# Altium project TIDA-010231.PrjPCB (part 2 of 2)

## Sheet TIDA-010231_Interface.SchDoc: Interface
size 431 x 279 mm; Date: Not shown in title block; ApprovedBy: Not shown in title block; CheckedBy: Not shown in title block; Author: Not shown in title block; CompanyName: Not shown in title block; Engineer: Not shown in title block; Organization: Not shown in title block; Address1: Not shown in title block; Address2: Not shown in title block; Address3: Not shown in title block; Address4: Not shown in title block; DocumentNumber: 5; Revision: Use project parameter SCH_Rev; SheetNumber: 5; SheetTotal: 6; PageSetup: Record=PageOptions¦CenterHorizontal=True¦CenterVertical=True¦PrintScale=1.00¦XCorrection=1.00¦YCorrection=1.00¦PrintKind=0¦BorderSize=5000000¦LeftOffset=0¦BottomOffset=0¦Orientation=2¦PaperLength=1000¦PaperWidth=1000¦Scale=100¦PaperSource=15¦PrintQuality=600¦MediaType=1¦DitherType=10¦PaperKind=Letter¦PrintScaleMode=1
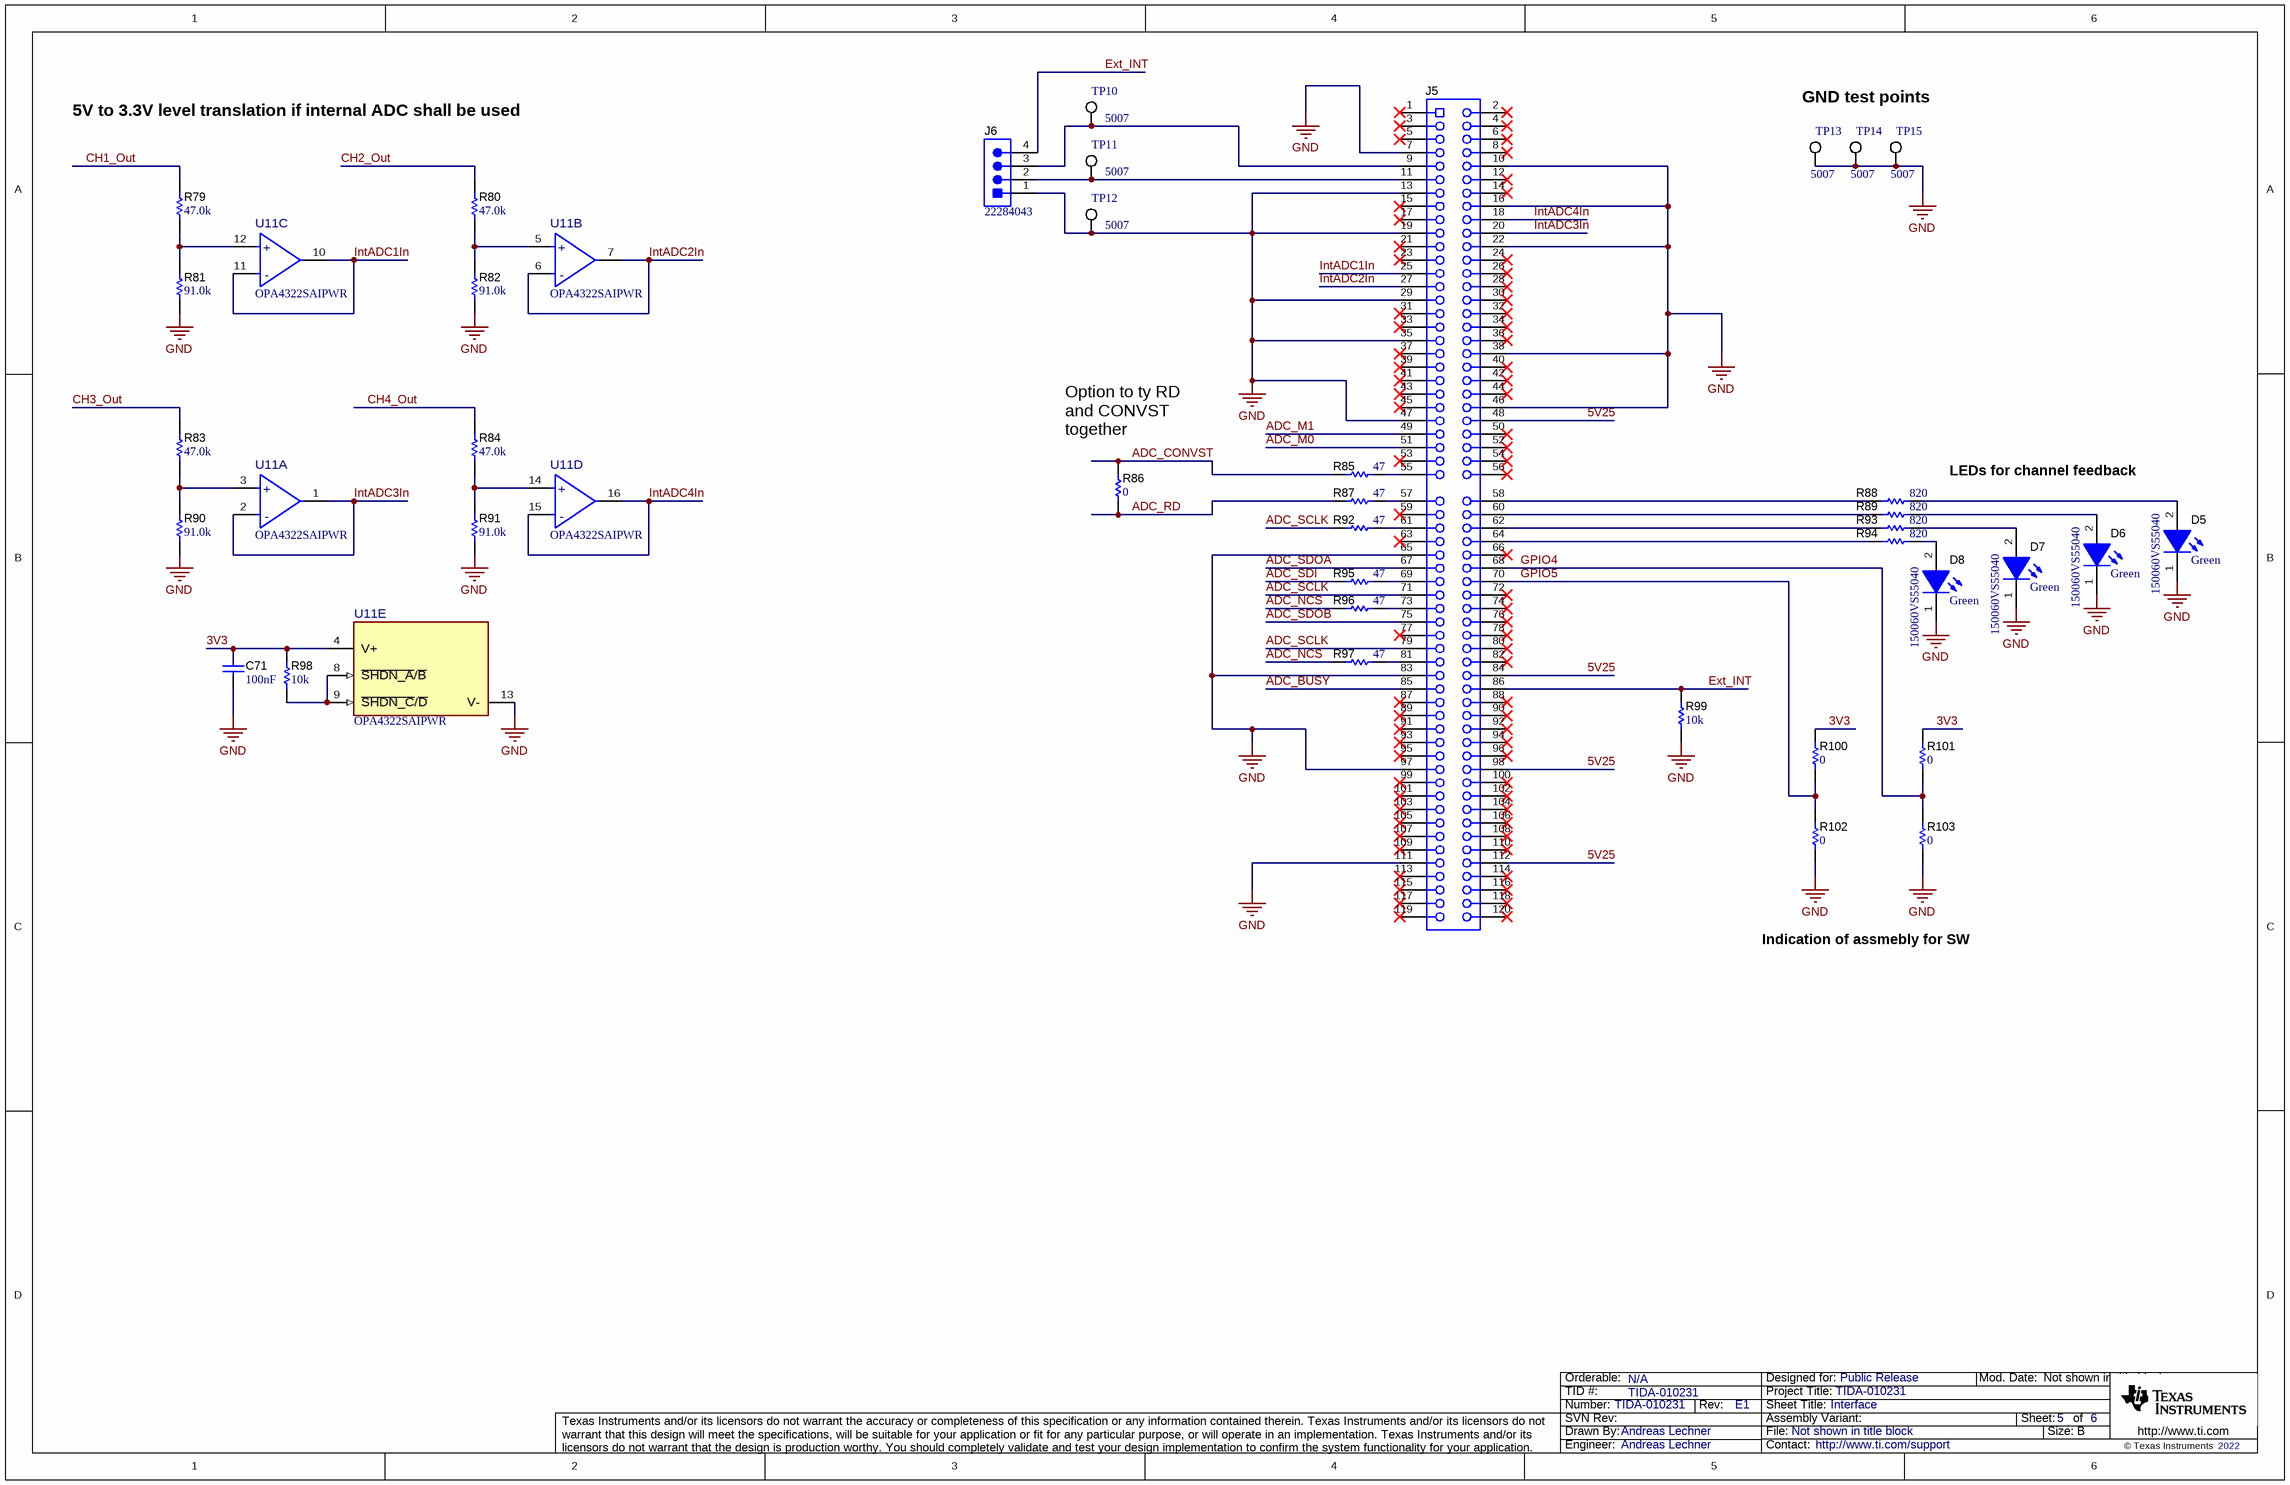
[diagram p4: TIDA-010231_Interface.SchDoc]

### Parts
C71  Cap_F: 100nF  [0603S]  (hidden comment: C0603C104K5RACAUTO)
D5  150060VS55040  value Green  [WL-SMCD-0603]
D6  150060VS55040  value Green  [WL-SMCD-0603]
D7  150060VS55040  value Green  [WL-SMCD-0603]
D8  150060VS55040  value Green  [WL-SMCD-0603]
J5  HSEC8-160-01-L-DV-A-BL  [controlCARD-120HSEC]  (value not drawn)
J6  22284043  [Molex_0022284043]
R79  ValueDisplayed: 47.0k  [0603S]  (hidden comment: CRCW060347K0FKEA)
R80  ValueDisplayed: 47.0k  [0603S]  (hidden comment: CRCW060347K0FKEA)
R81  ValueDisplayed: 91.0k  [0603S]  (hidden comment: RC0603FR-0791KL)
R82  ValueDisplayed: 91.0k  [0603S]  (hidden comment: RC0603FR-0791KL)
R83  ValueDisplayed: 47.0k  [0603S]  (hidden comment: CRCW060347K0FKEA)
R84  ValueDisplayed: 47.0k  [0603S]  (hidden comment: CRCW060347K0FKEA)
R85  ValueDisplayed: 47  [0402S]  (hidden comment: CRCW040247R0JNED)
R86  ValueDisplayed: 0  [0402S]  (hidden comment: CRCW04020000Z0ED)
R87  ValueDisplayed: 47  [0402S]  (hidden comment: CRCW040247R0JNED)
R88  ValueDisplayed: 820  [0603S]  (hidden comment: CRCW0603820RJNEA)
R89  ValueDisplayed: 820  [0603S]  (hidden comment: CRCW0603820RJNEA)
R90  ValueDisplayed: 91.0k  [0603S]  (hidden comment: RC0603FR-0791KL)
R91  ValueDisplayed: 91.0k  [0603S]  (hidden comment: RC0603FR-0791KL)
R92  ValueDisplayed: 47  [0402S]  (hidden comment: CRCW040247R0JNED)
R93  ValueDisplayed: 820  [0603S]  (hidden comment: CRCW0603820RJNEA)
R94  ValueDisplayed: 820  [0603S]  (hidden comment: CRCW0603820RJNEA)
R95  ValueDisplayed: 47  [0402S]  (hidden comment: CRCW040247R0JNED)
R96  ValueDisplayed: 47  [0402S]  (hidden comment: CRCW040247R0JNED)
R97  ValueDisplayed: 47  [0402S]  (hidden comment: CRCW040247R0JNED)
R98  ValueDisplayed: 10k  [0402S]  (hidden comment: CRCW040210K0JNED)
R99  ValueDisplayed: 10k  [0402S]  (hidden comment: CRCW040210K0JNED)
R100  ValueDisplayed: 0  [0603S]  (hidden comment: RMCF0603ZT0R00)
R101  ValueDisplayed: 0  [0603S]  (hidden comment: RMCF0603ZT0R00)
R102  ValueDisplayed: 0  [0603S]  (hidden comment: RMCF0603ZT0R00)
R103  ValueDisplayed: 0  [0603S]  (hidden comment: RMCF0603ZT0R00)
TP10  5007  [Keystone5007]
TP11  5007  [Keystone5007]
TP12  5007  [Keystone5007]
TP13  5007  [Keystone5007]
TP14  5007  [Keystone5007]
TP15  5007  [Keystone5007]
U11  OPA4322SAIPWR  [PW0016A-MFG]  (parts A,B,C,D,E of 5)

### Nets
GND: C71.2 D5.1(K) D6.1(K) D7.1(K) D8.1(K) J5.7 J5.10 J5.13 J5.16 J5.19 J5.22 J5.29 J5.35 J5.38 J5.46 J5.47 J5.65 J5.83 J5.97 J5.111 J6.1 R81.1 R82.1 R90.1 R91.1 R99.1 R102.1 R103.1 TP12.1 TP13.1 TP14.1 TP15.1 U11.13(V-)
3V3: C71.1 R98.2 R100.2 R101.1 U11.4(V+)
5V25: J5.48 J5.84 J5.98 J5.112
ADC_BUSY: J5.85
ADC_CONVST: R85.1 R86.2
ADC_M0: J5.51
ADC_M1: J5.49
ADC_NCS: R96.1 R97.1
ADC_RD: R86.1 R87.1
ADC_SCLK: J5.71 J5.79 R92.1
ADC_SDI: R95.1
ADC_SDOA: J5.67
ADC_SDOB: J5.75
CH1_Out: R79.2
CH2_Out: R80.2
CH3_Out: R83.2
CH4_Out: R84.2
Ext_INT: J5.86 J6.4 R99.2
GPIO4: J5.68 R101.2 R103.2
GPIO5: J5.70 R100.1 R102.2
IntADC1In: J5.25 U11.10(OUT_C) U11.11(-IN_C)
IntADC2In: J5.27 U11.6(-IN_B) U11.7(OUT_B)
IntADC3In: J5.20 U11.1(OUT_A) U11.2(-IN_A)
IntADC4In: J5.18 U11.15(-IN_D) U11.16(OUT_D)
NetD5_2: D5.2(A) R88.2
NetD6_2: D6.2(A) R89.2
NetD7_2: D7.2(A) R93.2
NetD8_2: D8.2(A) R94.2
NetJ5_9: J5.9 J6.3 TP10.1
NetJ5_11: J5.11 J6.2 TP11.1
NetJ5_55: J5.55 R85.2
NetJ5_57: J5.57 R87.2
NetJ5_58: J5.58 R88.1
NetJ5_60: J5.60 R89.1
NetJ5_61: J5.61 R92.2
NetJ5_62: J5.62 R93.1
NetJ5_64: J5.64 R94.1
NetJ5_69: J5.69 R95.2
NetJ5_73: J5.73 R96.2
NetJ5_81: J5.81 R97.2
NetR79_1: R79.1 R81.2 U11.12(+IN_C)
NetR80_1: R80.1 R82.2 U11.5(+IN_B)
NetR83_1: R83.1 R90.2 U11.3(+IN_A)
NetR84_1: R84.1 R91.2 U11.14(+IN_D)
NetR98_1: R98.1 U11.8(~{SHDN_A}/~{B}) U11.9(~{SHDN_C}/~{D})

Not connected (* = marked no-connect by the designer): J5 1* 2* 3* 4* 5* 6* 8* 12* 14* 15* 17* 21* 23* 24* 26* 28* 30* 31* 32* 33* 34* 36* 37* 39* 40* 41* 42* 43* 44* 45* 50* 52* 53* 54* 56* 59* 63* 66* 72* 74* 76* 77* 78* 80* 82* 87* 88* 89* 90* 91* 92* 93* 94* 95* 96* 99* 100* 101* 102* 103* 104* 105* 106* 107* 108* 109* 110* 113* 114* 115* 116* 117* 118* 119* 120*

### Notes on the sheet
- 5V to 3.3V level translation if internal ADC shall be used
- GND test points
- (near R86) Option to ty RD and CONVST together
- LEDs for channel feedback
- Indication of assmebly for SW

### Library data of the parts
C71 = CMP-0079602-1: CAP, CERM, 0.1 µF, 50 V,+/- 10%, X7R, AEC-Q200 Grade 1, 0603; Manufacturer: Kemet; TaMin_C: -55°C; Polarized: N; SizeAreaWB_mm2: 4.68; U/M: EA; Value: 0.1uF; TaMax_C: 125°C; SizeZ_mm: 1; SizeX_mm: 1.6; SizeY_mm: 0.8; Cap_Case: 0603; Value2: 50V; SizeArea_mm2: 1.28; AEC Qualified: Y; AEC Category: Q200; ValueDisplayed: 0.1µF
D5-D8 = CMP-0081648-2: LED, Green, SMD; Manufacturer: Wurth Elektronik; Type: AlInGaP; Vr_V: 5V; SizeZ_mm: 0.5; Tjmax_C: 115°C; Io_A: 20mA; Value1: 0.048W; Vf_V: 2V; SizeArea_mm2: 1.28; Angle: 140; SizeX_mm: 1.6; Ir_A: 10µA; Power_TotalModule: 48mW; SizeAreaWB_mm2: 4.68; SizeY_mm: 0.8
J5 = CMP-0003814-2: C2000 controlCARD-120HSEC connector, SMT; Manufacturer: Samtec; Note: The pin numbering does not match Samtec datasheet
J6 = CMP-0055331-1: Header, 2.54mm, 4x1, Tin, TH; Manufacturer: Molex; CNHeader: TRUE; Current_A: 4A; Shrouded: N; Gender: Male; Voltage_V: 250V; Row_Count: 1; Pitch_mm: 2.54; CT: FALSE; Cert_UL: Y
R79 R80 R83 R84 = CMP-0022438-4: RES, 47.0 k, 1%, 0.1 W, AEC-Q200 Grade 0, 0603; Manufacturer: Vishay-Dale; Power_W: 100mW; TempCo: 100 ppm/C; Value_Code: 47k0; Value: 47.0k; Res_ohm: 47k; SizeX_mm: 1.6; SizeY_mm: 0.8; SizeZ_mm: 1; Value2: 0.1W; SizeArea_mm2: 1.28; AEC Qualified: Y; AEC Grade: 0; AEC Category: Q200
R81 R82 R90 R91 = CMP-0023318-5: RES, 91.0 k, 1%, 0.1 W, 0603; Manufacturer: Yageo; Power_W: 100mW; TempCo: 100 ppm/C; Value_Code: 91k0; Value: 91.0k; Res_ohm: 91k; SizeX_mm: 1.6; SizeY_mm: 0.8; SizeZ_mm: 1; Value2: 0.1W; SizeArea_mm2: 1.28; AEC Qualified: N; AEC Category: Q200; SizeAreaWB_mm2: 4.68
R85 R87 R92 R95-R97 = CMP-0026936-3: RES, 47, 5%, 0.063 W, AEC-Q200 Grade 0, 0402; Manufacturer: Vishay-Dale; Power_W: 63mW; TempCo: 200 ppm/C; Value_Code: 47R0; Value: 47; EIA_Code: E24; SizeX_mm: 1; SizeY_mm: 0.5; SizeZ_mm: 0.6; Value2: 0.063W; AEC Qualified: Y; AEC Category: Q200; AEC Grade: 0
R86 = CMP-0026822-3: RES, 0, 5%, 0.063 W, AEC-Q200 Grade 0, 0402; Manufacturer: Vishay-Dale; Power_W: 63mW; TempCo: 200 ppm/C; Value_Code: 0000; Value: 0; EIA_Code: E24; SizeX_mm: 1; SizeY_mm: 0.5; SizeZ_mm: 0.6; Value2: 0.063W; AEC Qualified: Y; AEC Category: Q200
R88 R89 R93 R94 = CMP-0025859-4: RES, 820, 5%, 0.1 W, AEC-Q200 Grade 0, 0603; Manufacturer: Vishay-Dale; Power_W: 100mW; TempCo: 200 ppm/C; Value_Code: 820R; Value: 820; EIA_Code: E24; SizeX_mm: 1.6; SizeY_mm: 0.8; SizeZ_mm: 1; Value2: 0.1W; SizeArea_mm2: 1.28; AEC Qualified: Y; AEC Category: Q200; AEC Grade: 0
R98 R99 = CMP-0026825-5: RES, 10 k, 5%, 0.063 W, AEC-Q200 Grade 0, 0402; Manufacturer: Vishay-Dale; Power_W: 63mW; TempCo: 200 ppm/C; Value_Code: 10k0; Value: 10k; EIA_Code: E24; SizeX_mm: 1; SizeY_mm: 0.5; SizeZ_mm: 0.6; Value2: 0.063W; AEC Qualified: Y; AEC Category: Q200; AEC Grade: 0
R100-R103 = CMP-0023343-3: RES, 0, 1%, 0.1 W, AEC-Q200 Grade 0, 0603; Manufacturer: Stackpole Electronics Inc; Power_W: 100mW; TempCo: ppm/C; U/M: EA; Value: 0; SizeX_mm: 1.6; SizeY_mm: 0.8; SizeZ_mm: 1; Value2: 0.1W; SizeArea_mm2: 1.28; AEC Qualified: Y; AEC Category: Q200
TP10-TP15 = CMP-0055144-2: Test Point, Compact, White, TH; Manufacturer: Keystone Electronics; CNHeader: FALSE; Green_Lifecycle: Active; Green_REACh: Passed; ContactFinish: Silver; CT: TRUE
U11 = CMP-0093017-1: CMOS Amplifier 4 Circuit Rail-to-Rail 16-TSSOP; Manufacturer: Texas Instruments; TaMin_C: -40°C; Max Dual Supply Voltage: 2.75V; Voltage Gain: 130dB; Min Supply Voltage: 1.8V; TaMax_C: +125°C; Number Of Channels: 4; Input Bias Current: 0.0000002uA; AEC Qualified: No; TJmax_C: +150°C; Standoff Height: 0.05mm; Output Current Per Channel: 65mA; Response Time: 0.32us; Gain Bandwidth: 20MHz; Max Supply Voltage: 5.5V; Min Dual Supply Voltage: 900mV; Nominal Supply Current: 1.4mA; Ciiva Ids: 4369962; Import Ts: 1521861601; Input Offset Voltage: 0.5mV; SizeZ_mm: 1.2mm

## Sheet TIDA-010231_Hardware.SchDoc: Hardware
size 431 x 279 mm; Date: Not shown in title block; ApprovedBy: Not shown in title block; CheckedBy: Not shown in title block; Author: Not shown in title block; CompanyName: Not shown in title block; Engineer: Not shown in title block; Organization: Not shown in title block; Address1: Not shown in title block; Address2: Not shown in title block; Address3: Not shown in title block; Address4: Not shown in title block; DocumentNumber: 6; Revision: Use project parameter SCH_Rev; SheetNumber: 6; SheetTotal: 6; PageSetup: Record=PageOptions¦CenterHorizontal=True¦CenterVertical=True¦PrintScale=1.00¦XCorrection=1.00¦YCorrection=1.00¦PrintKind=0¦BorderSize=5000000¦LeftOffset=0¦BottomOffset=0¦Orientation=2¦PaperLength=1000¦PaperWidth=1000¦Scale=100¦PaperSource=15¦PrintQuality=600¦MediaType=1¦DitherType=10¦PaperKind=Letter¦PrintScaleMode=1
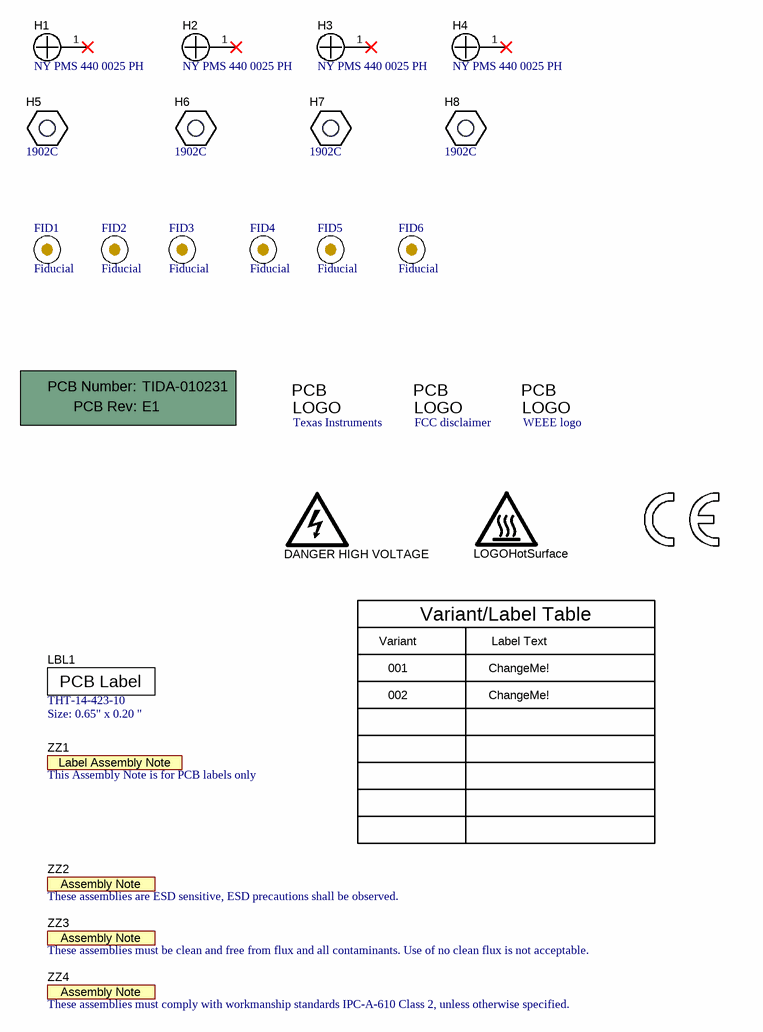
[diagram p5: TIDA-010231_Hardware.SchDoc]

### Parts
!PCB1  Printed Circuit Board  (value not drawn)  (mechanical)
FID1  Fiducial  [Fiducial10-30]
FID2  Fiducial  [Fiducial10-30]
FID3  Fiducial  [Fiducial10-30]
FID4  Fiducial  [Fiducial10-30]
FID5  Fiducial  [Fiducial10-30]
FID6  Fiducial  [Fiducial10-30]
H1  NY PMS 440 0025 PH  [NY PMS 440 0025 PH]
H2  NY PMS 440 0025 PH  [NY PMS 440 0025 PH]
H3  NY PMS 440 0025 PH  [NY PMS 440 0025 PH]
H4  NY PMS 440 0025 PH  [NY PMS 440 0025 PH]
H5  1902C  [Keystone_1902C]
H6  1902C  [Keystone_1902C]
H7  1902C  [Keystone_1902C]
H8  1902C  [Keystone_1902C]
LBL1  THT-14-423-10  Note: Size: 0.65" x 0.20 "  [Label_650x200]
Logo1  Texas Instruments  [TI_Stacked_Overlay_Small]  (no BOM)
Logo2  FCC disclaimer  [FCC_disclaimer]  (no BOM)
Logo3  WEEE logo  [WEEE_Minimum]  (no BOM)
LOGO_HV  DANGER HIGH VOLTAGE  [IEC_HighVoltage_Small]  (no BOM)
LogoCE  CE Mark  [CE_Mark_5mm]  (value not drawn)  (no BOM)
LOGOHotSurface  CAUTION HOT SURFACE  [IEC_HotSurface_Small]  (value not drawn)  (no BOM)
ZZ1  This Assembly Note is for PCB labels only  [AssemblyNoteLabel]  (no BOM)
ZZ2  These assemblies are ESD sensitive, ESD precautions shall be observed.  [AssemblyNote]  (no BOM)
ZZ3  These assemblies must be clean and free from flux and all contaminants. Use of no clean flux is not acceptable.  [AssemblyNote]  (no BOM)
ZZ4  These assemblies must comply with workmanship standards IPC-A-610 Class 2, unless otherwise specified.  [AssemblyNote]  (no BOM)

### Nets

Not connected (* = marked no-connect by the designer): H1 1*; H2 1*; H3 1*; H4 1*

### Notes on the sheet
- Variant
- Variant/Label Table
- Label Text
- 001
- 002
- ChangeMe!

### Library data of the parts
!PCB1 = CMP-0003618-2: Manufacturer: Any; PartNumber: TIDA-010231
FID1-FID6 = CMP-0077181-1: Fiducial mark.  There is nothing to buy or mount.
H1-H4 = CMP-0003617-1: Machine Screw, Round, #4-40 x 1/4, Nylon, Philips panhead; Manufacturer: B&F Fastener Supply; CompType: Hardware
H5-H8 = CMP-0003610-1: Standoff, Hex, 0.5"L #4-40 Nylon; Manufacturer: Keystone; CompType: Hardware
LBL1 = CMP-0003625-1: Thermal Transfer Printable Labels, 0.650" W x 0.200" H - 10,000 per roll; Manufacturer: Brady; CompType: Label
Logo1 = CMP-0074838-1: Texas Instrument Corporate Signature; SymbolCreator: a0412235; Lib Reference: TI_Logo; Library Reference: Logo
Logo2 = CMP-0074847-1: FCC_disclaimer; Library Reference: Logo
Logo3 = CMP-0074769-1
LOGO_HV = CMP-0074835-1: IEC 61010-1 High Voltage Warning; Library Reference: IEC_HighVoltage; SymbolCreator: a0412235
LogoCE = CMP-0074844-1: SymbolCreator: a0412235
LOGOHotSurface = CMP-0074837-2: IEC 61010-1 Hot Surface Warning; Manufacturer: Texas Instruments; SymbolCreator: a0412235; CompType: IC; AEC Category: Q200
ZZ1 = CMP-0003616-3
ZZ2 = CMP-0077236-1
ZZ3 = CMP-0077237-1
ZZ4 = CMP-0077238-1

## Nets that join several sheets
GND: TIDA-010231_Power (27 pins), TIDA-010231_Filter_and_ADC (50 pins), TIDA-010231_Current_Transformer (12 pins), TIDA-010231_Interface (33 pins)
2V5: TIDA-010231_Filter_and_ADC (35 pins), TIDA-010231_Current_Transformer (R120.1 R121.1 R122.1 R123.1)
3V3: TIDA-010231_Power (5 pins), TIDA-010231_Filter_and_ADC (R31.2), TIDA-010231_Interface (5 pins)
5V: TIDA-010231_Power (6 pins), TIDA-010231_Filter_and_ADC (15 pins), TIDA-010231_Current_Transformer (8 pins)
5V25: TIDA-010231_Power (8 pins), TIDA-010231_Interface (J5.48 J5.84 J5.98 J5.112)
ADC_BUSY: TIDA-010231_Filter_and_ADC (R46.2), TIDA-010231_Interface (J5.85)
ADC_CONVST: TIDA-010231_Filter_and_ADC (U7.19), TIDA-010231_Interface (R85.1 R86.2)
ADC_M0: TIDA-010231_Filter_and_ADC (R52.2 U7.17), TIDA-010231_Interface (J5.51)
ADC_M1: TIDA-010231_Filter_and_ADC (R51.2 U7.16), TIDA-010231_Interface (J5.49)
ADC_NCS: TIDA-010231_Filter_and_ADC (R42.1 U7.21), TIDA-010231_Interface (R96.1 R97.1)
ADC_RD: TIDA-010231_Filter_and_ADC (U7.20), TIDA-010231_Interface (R86.1 R87.1)
ADC_SCLK: TIDA-010231_Filter_and_ADC (R43.1 U7.22), TIDA-010231_Interface (J5.71 J5.79 R92.1)
ADC_SDI: TIDA-010231_Filter_and_ADC (U7.18), TIDA-010231_Interface (R95.1)
ADC_SDOA: TIDA-010231_Filter_and_ADC (R47.2), TIDA-010231_Interface (J5.67)
ADC_SDOB: TIDA-010231_Filter_and_ADC (R48.2), TIDA-010231_Interface (J5.75)
CH1_Filt_In: TIDA-010231_Filter_and_ADC (R23.1 R30.2 TP2.1), TIDA-010231_Current_Transformer (R2.2 U1.1)
CH1_Out: TIDA-010231_Filter_and_ADC (R27.2 R30.1 R39.1), TIDA-010231_Interface (R79.2)
CH2_Filt_In: TIDA-010231_Filter_and_ADC (R34.1 R44.2 TP4.1), TIDA-010231_Current_Transformer (R7.2 U2.1)
CH2_Out: TIDA-010231_Filter_and_ADC (R38.2 R44.1 R45.1), TIDA-010231_Interface (R80.2)
CH3_Filt_In: TIDA-010231_Filter_and_ADC (R53.1 R61.2 TP6.1), TIDA-010231_Current_Transformer (R12.2 U3.1)
CH3_Out: TIDA-010231_Filter_and_ADC (R57.2 R60.1 R61.1), TIDA-010231_Interface (R83.2)
CH4_Filt_In: TIDA-010231_Filter_and_ADC (R65.1 R72.2 TP7.1), TIDA-010231_Current_Transformer (R17.2 U4.1)
CH4_Out: TIDA-010231_Filter_and_ADC (R62.1 R69.1 R72.1), TIDA-010231_Interface (R84.2)

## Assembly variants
001: not fitted C35 C94 C100 C106 C112 R30 R43 R44 R61 R72 R100 R101 R102 R103 R118 R119 R128 R134 R140 R146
